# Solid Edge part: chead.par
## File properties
Title: Cross Head
Subject: Carrier Assembly
Author: Dwight Yorke
Keywords: Block
Comments: Cross Head
Template: metric.par
Last saved by: rkriggs
Revision: 64
Application: Solid Edge
Category: Machined Block
Manager: Brian Little
Company: Wheels R Us
Density: 7702
Accuracy: 0.00
File Size: 0
Number of Sheets: 0
Number of Objects: 0
Document Number: C-3701
Revision: 1
Project Name: Trolley Wheel Assembly
Material: Bronze, 90%
Face Style: Bronze
Fill Style: ANSI33(Brass)
Virtual Style: Brushed bronze
Coef. of Thermal Exp: 1.8e-05
Thermal Conductivity: 189.0
Specific Heat: 377.0
Modulus of Elasticity: 117210869000.0
Poisson's Ratio: 0.36
Yield Stress: 372316878.0
Ultimate Stress: 420580177.0
Elongation: 0.0
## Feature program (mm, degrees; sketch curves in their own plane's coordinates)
sketch for "unnamed Protrusion 1" plane through (0, 0, 0) normal (0, -1, 0) x-axis (1, 0, 0)
  line (-53.3125, 21.0114) -> (66.6875, 21.0114)
  line (66.6875, 21.0114) -> (66.6875, -28.9886)
  line (66.6875, -28.9886) -> (-53.3125, -28.9886)
  line (-53.3125, -28.9886) -> (-53.3125, 21.0114)
extrude "unnamed Protrusion 1" add finite 140 along -normal
sketch for "unnamed Hole 1" plane through (6.6875, 0, -3.9886) normal (0, -1, 0) x-axis (1, 0, 0)
  hole centre (30, 0) bore radius 10
hole "unnamed Hole 1" through
sketch for "Hole_2" plane through (6.6875, 0, -3.9886) normal (0, -1, 0) x-axis (1, 0, 0)
  hole centre (-30, 0) bore radius 10
hole "Hole_2" through
pattern "unnamed Pattern 1" of "unnamed Hole 1", "Hole_2"
sketch for "Hole_3" plane through (6.6875, 70, 21.0114) normal (0, 0, 1) x-axis (1, 0, 0)
  hole centre (0, 0) bore radius 10
hole "Hole_3" through  CounterBoreDepth = 12 mm
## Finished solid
Body 1: solid body, 11 faces, 20 edges, 8 vertices.
  Faces by surface: plane 7, cylinder 4
  Edges by curve: line 12, circle 8
Bounding box of the edges (mm): 120.000 x 140.000 x 50.000, from (-53.3125, 0, -28.9886) to (66.6875, 140, 21.0114).
Cylindrical faces by radius (mm): R10 x3, R18 x1
Planar faces by outward normal: +x 1, +y 1, +z 2, -x 1, -y 1, -z 1
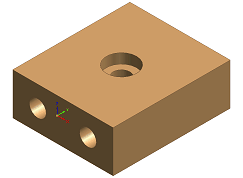
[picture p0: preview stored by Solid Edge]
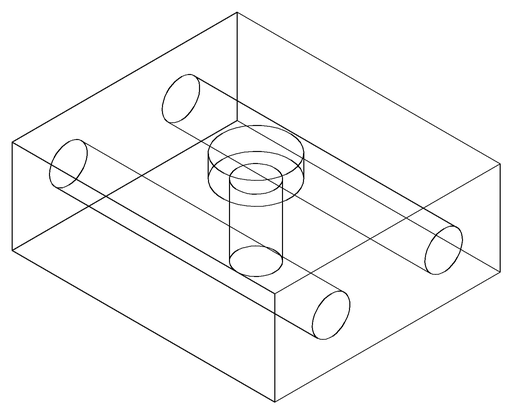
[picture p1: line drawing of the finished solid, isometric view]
